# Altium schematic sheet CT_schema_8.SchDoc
size 287 x 160 mm
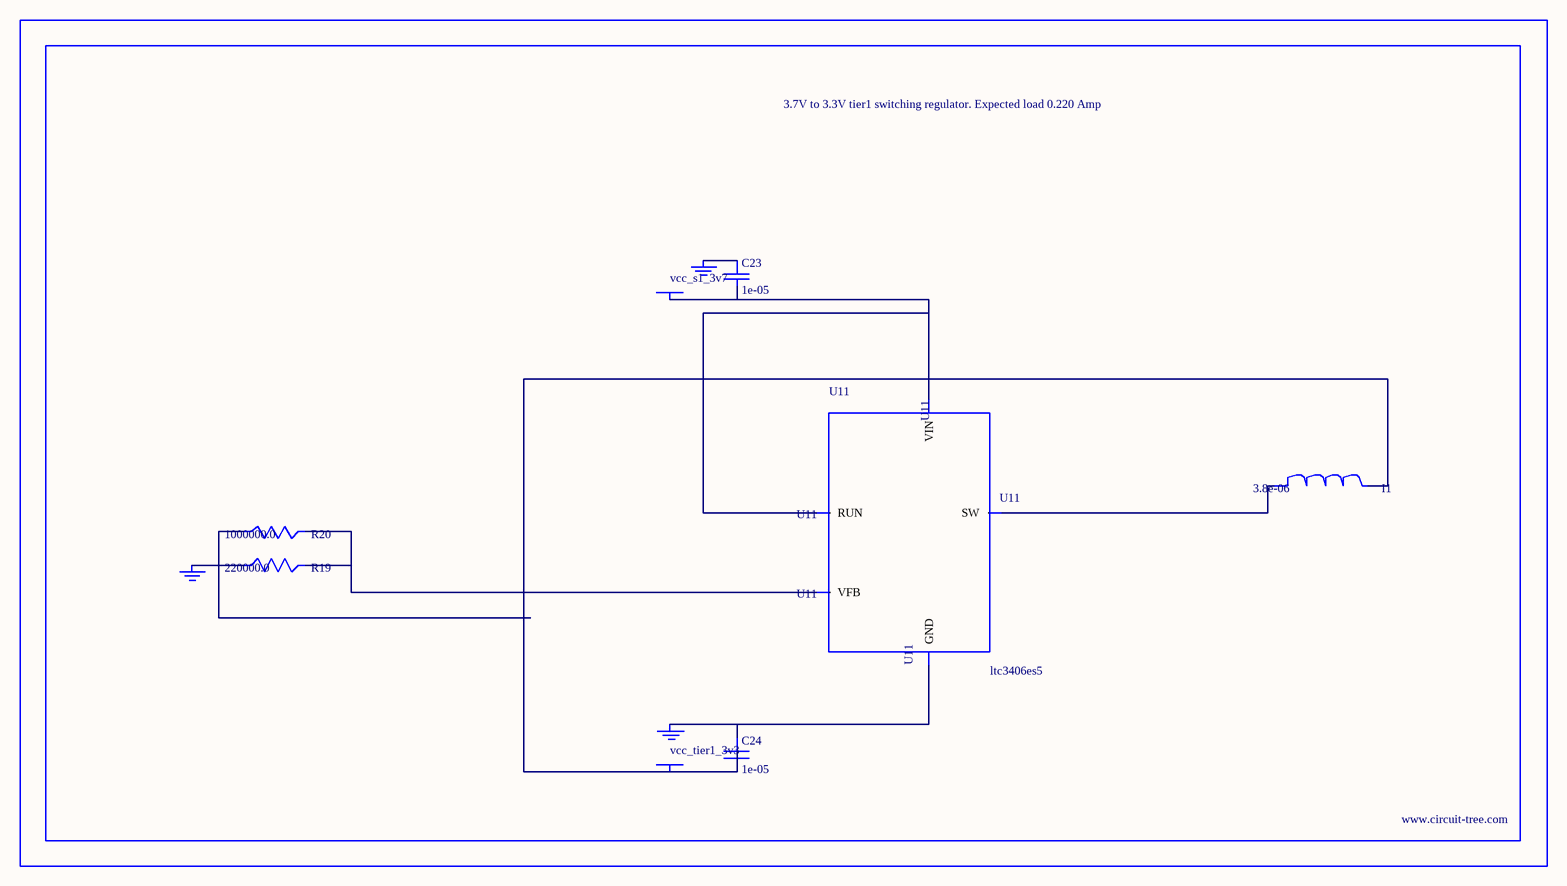
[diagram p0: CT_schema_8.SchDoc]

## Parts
BORDER7  (no value)
C23  1e-05  [C0805]
C24  1e-05  [C0805]
GND_INSTANCE_7_0  (no value)
GND_INSTANCE_7_1  (no value)
GND_INSTANCE_7_2  (no value)
I1  3.8e-06  [DR1040]
POWER_INSTANCE_7_0  vcc_tier1_3v3
POWER_INSTANCE_7_1  vcc_s1_3v7
R19  220000.0  [R0603]
R20  1000000.0  [R0603]
U11  ltc3406es5  [TSOT-23-5]

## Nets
NetC23_1: C23.1 GND_INSTANCE_7_1.0(GND)
NetC23_2: C23.2 POWER_INSTANCE_7_1.0(PWR) U11.1(RUN) U11.4(VIN)
NetC24_1: C24.1 GND_INSTANCE_7_0.0(GND) U11.2(GND)
NetC24_2: C24.2 I1.2 POWER_INSTANCE_7_0.0(PWR) R20.1
NetGND_INSTANCE_7_2_0: GND_INSTANCE_7_2.0(GND) R19.1
NetI1_1: I1.1 U11.3(SW)
NetR19_2: R19.2 R20.2 U11.5(VFB)

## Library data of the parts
BORDER7 = BORDER_PAGE7
C23 C24 = C0805C106K8RACTU
GND_INSTANCE_7_0-GND_INSTANCE_7_2 = GND
I1 = DR1040-3R8-R
POWER_INSTANCE_7_0 POWER_INSTANCE_7_1 = PWR
R19 = RC0603JR-07220KL
R20 = RC0603JR-071ML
